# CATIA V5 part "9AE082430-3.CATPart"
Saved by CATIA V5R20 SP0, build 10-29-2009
Part number: 9AE082430-3
Revision: ANY
Definition: UNKNOWN
Nomenclature: 9AE082430-3
Source: Unknown
Bounding box of the stored display mesh (mm): x -14.75 to 14.75, y 0 to 68.999, z -14.75 to 14.75
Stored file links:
  C:\Users\Utente\Desktop\IO LAVORO\3D X SITO CF\CUMSA\3D files AE\AE 082430\9AE082430-3.CATPart
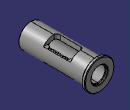
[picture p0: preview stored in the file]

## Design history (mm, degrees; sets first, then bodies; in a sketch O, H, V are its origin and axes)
Body1 "Cortar-Barrer1" (main body)
  Solid1: solid without history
